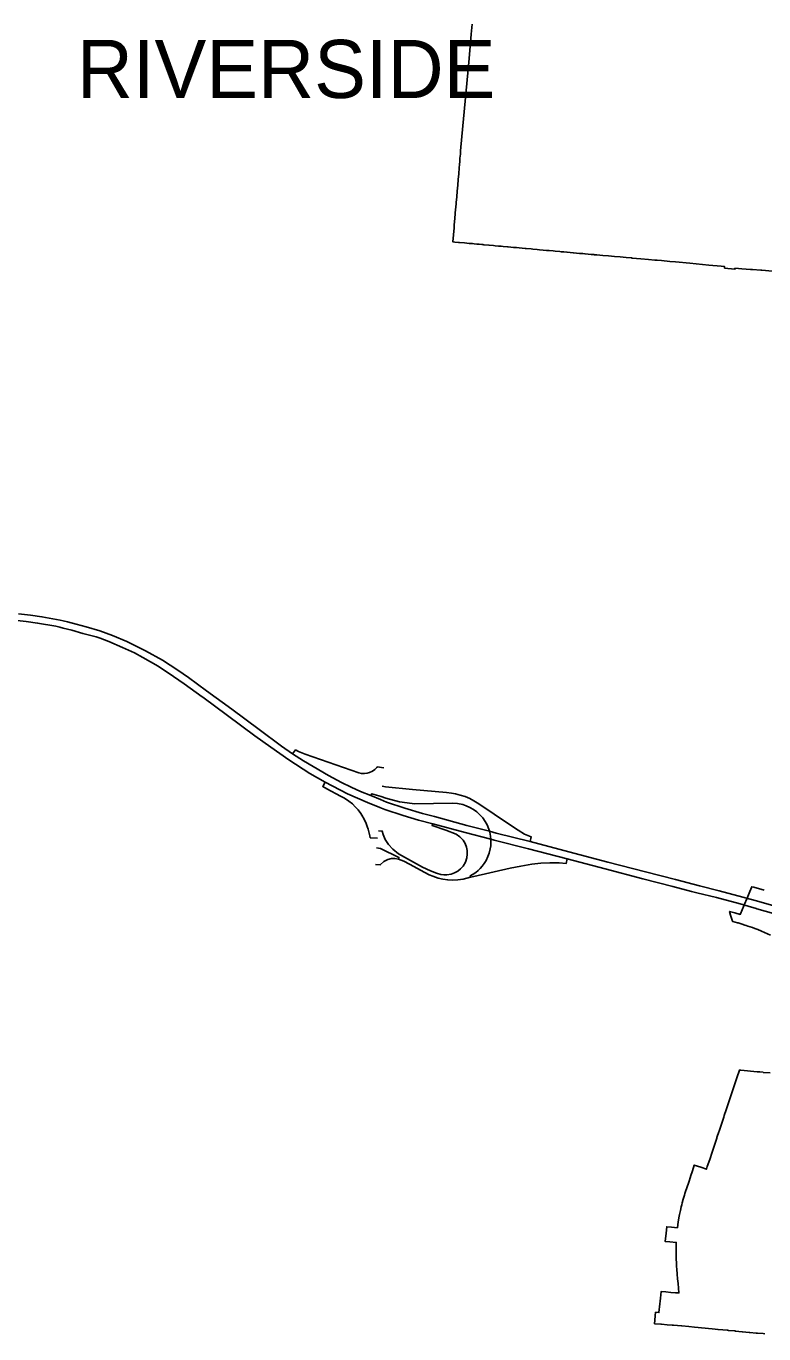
# Model space of a CAD drawing. Extents: x 0 to 34, y 0 to 22.
# Drawn here: x 5.4877 to 5.5898, y 15.0349 to 15.2158 of the extents above; entities that cross this region are included whole.
import ezdxf

# ---------------------------------------------------------------- set-up
doc = ezdxf.new("R2010")
doc.units = 0
for name, color, linetype in [('GM_X_Corporation', 7, 'Continuous'), ('GM_X_Corporation_Text', 7, 'Continuous'), ('GM_X_Interchange_Ramps', 7, 'Continuous'), ('GM_X_US_Route', 7, 'Continuous')]:
    doc.layers.add(name, color=color, linetype=linetype)

msp = doc.modelspace()

# ---------------------------------------------------------------- linework, layer by layer
at = {"layer": 'GM_X_Corporation'}
for points in [[(5.591, 15.18195), (5.5895, 15.18206), (5.58938, 15.18207), (5.58821, 15.18215), (5.58795, 15.18217), (5.58675, 15.18225), (5.58628, 15.18229), (5.58627, 15.18229), (5.58579, 15.18233), (5.58578, 15.18221), (5.58435, 15.18235), (5.58436, 15.18257), (5.58388, 15.18261), (5.58217, 15.18277), (5.57957, 15.18302), (5.57757, 15.18321), (5.57756, 15.18321), (5.57677, 15.18328), (5.57562, 15.18339), (5.57505, 15.18344), (5.57502, 15.18345), (5.57499, 15.18345), (5.57496, 15.18345), (5.57472, 15.18347), (5.57382, 15.18355), (5.57279, 15.18364), (5.57156, 15.18375), (5.57146, 15.18376), (5.57075, 15.18382), (5.56993, 15.1839), (5.56912, 15.18397), (5.56831, 15.18404), (5.5675, 15.18411), (5.56668, 15.18418), (5.5663, 15.18421), (5.56588, 15.18425), (5.56508, 15.18433), (5.56502, 15.18433), (5.56476, 15.18436), (5.56427, 15.1844), (5.56345, 15.18447), (5.56342, 15.18448), (5.56259, 15.18455), (5.56251, 15.18456), (5.56211, 15.18459), (5.56175, 15.18463), (5.56157, 15.18464), (5.56092, 15.1847), (5.56064, 15.18473), (5.56009, 15.18478), (5.5597, 15.18481), (5.55926, 15.18485), (5.55876, 15.1849), (5.55842, 15.18493), (5.55783, 15.18498), (5.55759, 15.185), (5.55689, 15.18507), (5.55676, 15.18508), (5.55595, 15.18515), (5.55555, 15.18519), (5.55555, 15.18519), (5.55515, 15.18522), (5.5544, 15.18529), (5.5543, 15.1853), (5.55373, 15.18535), (5.55346, 15.18538), (5.55306, 15.18541), (5.55261, 15.18545), (5.55238, 15.18547), (5.55176, 15.18553), (5.55171, 15.18553), (5.55104, 15.18559), (5.55091, 15.18561), (5.55074, 15.18562), (5.55037, 15.18566), (5.55006, 15.18568), (5.5497, 15.18572), (5.54946, 15.18574), (5.54921, 15.18576), (5.54903, 15.18578), (5.54837, 15.18584), (5.54836, 15.18584), (5.54768, 15.1859), (5.54755, 15.18591), (5.54701, 15.18596), (5.54701, 15.18596), (5.54675, 15.18598), (5.54675, 15.18598), (5.54675, 15.18599), (5.54692, 15.18793), (5.54695, 15.18835), (5.54698, 15.18874), (5.54708, 15.18983), (5.54714, 15.19058), (5.54715, 15.19063), (5.54721, 15.19143), (5.54728, 15.19222), (5.54735, 15.19302), (5.54742, 15.19382), (5.54749, 15.19462), (5.54756, 15.19542), (5.54762, 15.19621), (5.54766, 15.19668), (5.5477, 15.19712), (5.54774, 15.19755), (5.54779, 15.19812), (5.54783, 15.19859), (5.548, 15.20057), (5.54882, 15.20937), (5.54895, 15.21083), (5.54929, 15.21467), (5.54929, 15.2147), (5.54942, 15.2161)], [(5.54942, 15.2161), (5.54929, 15.2147), (5.54929, 15.21467), (5.54895, 15.21083), (5.54882, 15.20937), (5.548, 15.20058), (5.54783, 15.19859), (5.54779, 15.19812), (5.54774, 15.19755), (5.5477, 15.19713), (5.54766, 15.19668), (5.54762, 15.19621), (5.54756, 15.19542), (5.54749, 15.19462), (5.54742, 15.19382), (5.54735, 15.19302), (5.54728, 15.19222), (5.54721, 15.19143), (5.54715, 15.19063), (5.54714, 15.19058), (5.54708, 15.18983), (5.54698, 15.18874), (5.54695, 15.18835), (5.54692, 15.18793), (5.54692, 15.18793), (5.54675, 15.18599), (5.54675, 15.18598), (5.54675, 15.18598), (5.54701, 15.18596), (5.54701, 15.18596), (5.54755, 15.18591), (5.54768, 15.1859), (5.54836, 15.18584), (5.54837, 15.18584), (5.54903, 15.18578), (5.54921, 15.18576), (5.54946, 15.18574), (5.5497, 15.18572), (5.55006, 15.18568), (5.55037, 15.18566), (5.55074, 15.18562), (5.55091, 15.18561), (5.55104, 15.18559), (5.55171, 15.18553), (5.55176, 15.18553), (5.55238, 15.18547), (5.55261, 15.18545), (5.55306, 15.18541), (5.55346, 15.18538), (5.55373, 15.18535), (5.5543, 15.1853), (5.5544, 15.18529), (5.55515, 15.18522), (5.55555, 15.18519), (5.55555, 15.18519), (5.55595, 15.18515), (5.55676, 15.18508), (5.55689, 15.18507), (5.55759, 15.185), (5.55783, 15.18498), (5.55842, 15.18493), (5.55876, 15.1849), (5.55926, 15.18485), (5.5597, 15.18481), (5.56009, 15.18478), (5.56064, 15.18473), (5.56092, 15.1847), (5.56157, 15.18464), (5.56175, 15.18463), (5.56211, 15.18459), (5.56251, 15.18456), (5.56259, 15.18455), (5.56342, 15.18448), (5.56345, 15.18447), (5.56427, 15.1844), (5.56476, 15.18436), (5.56502, 15.18433), (5.56508, 15.18433), (5.56588, 15.18425), (5.5663, 15.18422), (5.56668, 15.18418), (5.5675, 15.18411), (5.56831, 15.18404), (5.56912, 15.18397), (5.56993, 15.1839), (5.57075, 15.18382), (5.57146, 15.18376), (5.57156, 15.18375), (5.57279, 15.18364), (5.57382, 15.18355), (5.57472, 15.18347), (5.57496, 15.18345), (5.57499, 15.18345), (5.57502, 15.18345), (5.57505, 15.18344), (5.57562, 15.18339), (5.57677, 15.18328), (5.57756, 15.18321), (5.57757, 15.18321), (5.57957, 15.18302), (5.58217, 15.18277), (5.58388, 15.18261), (5.58436, 15.18257), (5.58435, 15.18235), (5.58578, 15.18221), (5.58579, 15.18233), (5.58627, 15.18229), (5.58628, 15.18229), (5.58675, 15.18226), (5.58675, 15.18226), (5.58795, 15.18217), (5.58821, 15.18215), (5.58938, 15.18207), (5.5895, 15.18206), (5.591, 15.18195)], [(5.59072, 15.09008), (5.58946, 15.09064), (5.58897, 15.09085), (5.58855, 15.091), (5.58824, 15.09112), (5.58756, 15.09134), (5.58735, 15.09142), (5.58714, 15.09148), (5.58679, 15.0916), (5.58652, 15.09168), (5.58623, 15.09177), (5.58616, 15.0918), (5.58552, 15.09198), (5.58545, 15.09199), (5.58545, 15.092), (5.58545, 15.092), (5.5852, 15.09286), (5.58506, 15.09336), (5.5858, 15.09316), (5.58653, 15.09294), (5.58656, 15.09301), (5.58703, 15.09414), (5.58708, 15.09426), (5.58747, 15.0952), (5.58785, 15.09613), (5.58812, 15.09678), (5.58841, 15.0967), (5.58983, 15.09629)], [(5.58983, 15.09629), (5.58841, 15.0967), (5.58812, 15.09678), (5.58785, 15.09613), (5.58747, 15.0952), (5.58708, 15.09426), (5.58703, 15.09414), (5.58656, 15.09301), (5.58653, 15.09294), (5.5858, 15.09316), (5.58506, 15.09336), (5.5852, 15.09286), (5.58545, 15.092), (5.58545, 15.09199), (5.58552, 15.09198), (5.58616, 15.0918), (5.58623, 15.09177), (5.58652, 15.09168), (5.58679, 15.0916), (5.58714, 15.09148), (5.58735, 15.09142), (5.58756, 15.09134), (5.58824, 15.09112), (5.58855, 15.091), (5.58897, 15.09085), (5.58946, 15.09064), (5.59072, 15.09008)], [(5.58994, 15.03492), (5.5897, 15.03495), (5.5889, 15.03502), (5.58874, 15.03504), (5.58786, 15.03512), (5.58777, 15.03513), (5.58682, 15.03522), (5.58681, 15.03522), (5.58585, 15.03531), (5.58578, 15.03532), (5.58489, 15.0354), (5.58474, 15.03542), (5.58346, 15.03554), (5.58344, 15.03554), (5.58304, 15.03559), (5.58263, 15.03563), (5.5802, 15.03586), (5.57939, 15.03594), (5.57843, 15.03602), (5.57841, 15.03603), (5.57841, 15.03603), (5.57731, 15.03612), (5.57729, 15.03612), (5.5771, 15.03613), (5.57641, 15.03619), (5.57565, 15.03625), (5.57552, 15.03626), (5.57468, 15.03633), (5.57482, 15.03791), (5.57528, 15.03787), (5.57532, 15.03827), (5.57532, 15.03829), (5.57536, 15.03867), (5.57547, 15.03987), (5.57556, 15.04077), (5.57623, 15.04072), (5.5769, 15.04066), (5.57758, 15.04061), (5.57803, 15.04058), (5.57797, 15.04124), (5.57792, 15.04189), (5.57786, 15.04255), (5.5778, 15.0432), (5.57774, 15.04385), (5.57771, 15.04424), (5.57769, 15.04463), (5.57766, 15.04538), (5.57765, 15.04593), (5.57765, 15.04596), (5.57765, 15.04648), (5.57766, 15.04702), (5.57767, 15.04756), (5.57767, 15.04757), (5.57767, 15.04757), (5.5768, 15.04764), (5.57615, 15.04769), (5.57614, 15.04769), (5.57626, 15.04887), (5.57635, 15.04975), (5.577, 15.04969), (5.57783, 15.04961), (5.57787, 15.05001), (5.57792, 15.05041), (5.57807, 15.0512), (5.57812, 15.05145), (5.57824, 15.05198), (5.57836, 15.05251), (5.57843, 15.05278), (5.5785, 15.05304), (5.57864, 15.05357), (5.5788, 15.05409), (5.57888, 15.05435), (5.57896, 15.05461), (5.57913, 15.05513), (5.57939, 15.05592), (5.57963, 15.05666), (5.57965, 15.0567), (5.57991, 15.05748), (5.58017, 15.05826), (5.58109, 15.05796), (5.58185, 15.0577), (5.58197, 15.05808), (5.5823, 15.05906), (5.58262, 15.06004), (5.58295, 15.06101), (5.58309, 15.06145), (5.58327, 15.06199), (5.5833, 15.06207), (5.58356, 15.06286), (5.5836, 15.06297), (5.58392, 15.06395), (5.58425, 15.06492), (5.58432, 15.06514), (5.58458, 15.0659), (5.5849, 15.06688), (5.58496, 15.06704), (5.58532, 15.06813), (5.58569, 15.06923), (5.58605, 15.07033), (5.58642, 15.07142), (5.5866, 15.0714), (5.58887, 15.07118), (5.58924, 15.07115), (5.58969, 15.07111), (5.58972, 15.0711), (5.59069, 15.07101)], [(5.59069, 15.07101), (5.58972, 15.0711), (5.58969, 15.07111), (5.58924, 15.07115), (5.58887, 15.07118), (5.5866, 15.0714), (5.58642, 15.07142), (5.58605, 15.07033), (5.58569, 15.06923), (5.58532, 15.06813), (5.58496, 15.06704), (5.5849, 15.06688), (5.58458, 15.0659), (5.58432, 15.06514), (5.58425, 15.06492), (5.58392, 15.06395), (5.5836, 15.06297), (5.58356, 15.06286), (5.5833, 15.06207), (5.58327, 15.06199), (5.58309, 15.06145), (5.58295, 15.06101), (5.58262, 15.06004), (5.5823, 15.05906), (5.58197, 15.05808), (5.58185, 15.0577), (5.58109, 15.05796), (5.58017, 15.05826), (5.57991, 15.05748), (5.57965, 15.0567), (5.57963, 15.05666), (5.57939, 15.05592), (5.57913, 15.05513), (5.57896, 15.05461), (5.57888, 15.05435), (5.5788, 15.05409), (5.57864, 15.05357), (5.5785, 15.05304), (5.57843, 15.05278), (5.57836, 15.05251), (5.57824, 15.05198), (5.57812, 15.05145), (5.57807, 15.0512), (5.57792, 15.05041), (5.57787, 15.05001), (5.57783, 15.04961), (5.577, 15.04969), (5.57635, 15.04975), (5.57626, 15.04887), (5.57614, 15.04769), (5.57615, 15.04769), (5.5768, 15.04764), (5.57767, 15.04757), (5.57767, 15.04757), (5.57767, 15.04756), (5.57766, 15.04702), (5.57765, 15.04648), (5.57765, 15.04596), (5.57765, 15.04593), (5.57766, 15.04538), (5.57769, 15.04463), (5.57771, 15.04424), (5.57774, 15.04385), (5.5778, 15.0432), (5.57786, 15.04255), (5.57792, 15.04189), (5.57797, 15.04124), (5.57803, 15.04058), (5.57758, 15.04061), (5.5769, 15.04066), (5.57623, 15.04072), (5.57556, 15.04077), (5.57547, 15.03987), (5.57536, 15.03867), (5.57532, 15.03829), (5.57532, 15.03827), (5.57528, 15.03787), (5.57482, 15.03791), (5.57468, 15.03633), (5.57552, 15.03626), (5.57565, 15.03625), (5.57641, 15.03619), (5.5771, 15.03613), (5.57729, 15.03612), (5.57731, 15.03612), (5.57841, 15.03603), (5.57841, 15.03603), (5.57843, 15.03602), (5.57939, 15.03594), (5.5802, 15.03586), (5.58263, 15.03563), (5.58304, 15.03559), (5.58344, 15.03554), (5.58346, 15.03554), (5.58474, 15.03542), (5.58489, 15.0354), (5.58578, 15.03532), (5.58585, 15.03531), (5.58681, 15.03522), (5.58682, 15.03522), (5.58777, 15.03513), (5.58786, 15.03512), (5.58874, 15.03504), (5.5889, 15.03502), (5.5897, 15.03495), (5.58994, 15.03492)]]:
    msp.add_lwpolyline(points, dxfattribs=at)
at = {"layer": 'GM_X_Interchange_Ramps'}
for points in [[(5.5372, 15.11324), (5.53628, 15.11336), (5.53621, 15.11326), (5.53593, 15.11298), (5.53564, 15.11277), (5.53523, 15.11257), (5.53488, 15.11247), (5.53453, 15.11242), (5.53409, 15.11244), (5.53373, 15.11253), (5.52633, 15.11511), (5.5254, 15.11547), (5.52498, 15.1157), (5.52456, 15.11518)], [(5.5291, 15.11123), (5.52874, 15.11063), (5.52931, 15.1103), (5.5312, 15.10932), (5.53176, 15.10903), (5.53236, 15.10863), (5.53285, 15.10824), (5.53325, 15.10785), (5.53365, 15.10741), (5.53403, 15.1069), (5.53431, 15.10645), (5.53436, 15.10635)], [(5.5492, 15.09809), (5.54916, 15.09827), (5.54958, 15.09852), (5.54992, 15.09876), (5.55025, 15.09903), (5.55054, 15.09931), (5.55081, 15.09961), (5.55108, 15.09998), (5.55136, 15.10042), (5.55161, 15.10094), (5.55178, 15.1014), (5.55193, 15.10202), (5.55199, 15.10243), (5.55202, 15.10301), (5.55201, 15.10334), (5.55197, 15.10373), (5.55191, 15.10411), (5.55181, 15.10445), (5.55174, 15.10473), (5.55149, 15.10532), (5.55122, 15.10581), (5.55088, 15.1063), (5.55049, 15.10674), (5.55005, 15.10714), (5.5496, 15.10747), (5.54912, 15.10775), (5.5486, 15.10798), (5.54814, 15.10813), (5.54738, 15.10829), (5.54669, 15.10836), (5.54142, 15.10826), (5.54042, 15.10838), (5.53938, 15.10853), (5.53748, 15.10905), (5.53681, 15.10926), (5.53556, 15.10964), (5.53542, 15.10938)], [(5.54117, 15.11024), (5.53742, 15.11061), (5.53695, 15.11068)], [(5.55745, 15.10302), (5.55761, 15.10367), (5.55665, 15.10407), (5.55578, 15.10459), (5.55461, 15.1054), (5.55033, 15.10826), (5.54967, 15.10867), (5.54908, 15.10898), (5.54845, 15.10924), (5.54778, 15.10946), (5.54714, 15.10962), (5.54657, 15.10972), (5.54585, 15.10979), (5.54117, 15.11024)], [(5.53436, 15.10635), (5.53458, 15.10594), (5.53475, 15.10554), (5.5349, 15.10513), (5.53502, 15.10473), (5.53526, 15.10383), (5.53532, 15.10355), (5.53633, 15.10349)], [(5.54398, 15.10548), (5.54387, 15.10525), (5.54579, 15.10462), (5.54722, 15.10405), (5.54773, 15.10368), (5.54816, 15.10321), (5.54844, 15.10274), (5.54863, 15.10224), (5.54872, 15.10177), (5.54874, 15.10129), (5.54867, 15.10077), (5.54848, 15.10019), (5.54816, 15.09964), (5.54783, 15.09926), (5.54745, 15.09895), (5.54698, 15.09868), (5.5465, 15.0985), (5.54591, 15.09841), (5.5455, 15.09841), (5.5451, 15.09846), (5.54447, 15.09867), (5.54367, 15.09896), (5.54254, 15.09947), (5.53925, 15.10135), (5.53845, 15.10196), (5.53785, 15.1026), (5.5374, 15.10333), (5.5371, 15.10398), (5.53698, 15.10447), (5.53644, 15.10451)], [(5.5362, 15.10214), (5.53676, 15.10208), (5.53928, 15.10084), (5.53923, 15.10057)], [(5.53605, 15.09987), (5.53671, 15.0998), (5.53718, 15.10026), (5.53777, 15.10053), (5.53824, 15.10068), (5.53871, 15.10067), (5.53923, 15.10057), (5.53997, 15.10031), (5.54076, 15.09989), (5.54287, 15.09874), (5.54349, 15.09843), (5.54398, 15.09823), (5.54473, 15.09798), (5.54538, 15.09783), (5.54604, 15.09772), (5.54671, 15.09767), (5.54746, 15.09772), (5.54817, 15.09783), (5.5492, 15.09809), (5.54965, 15.0982), (5.55468, 15.09933), (5.55618, 15.09962), (5.55766, 15.09989), (5.55894, 15.10004), (5.56019, 15.10009), (5.56146, 15.10009), (5.56242, 15.09999), (5.56258, 15.10063)]]:
    msp.add_lwpolyline(points, dxfattribs=at)
at = {"layer": 'GM_X_US_Route'}
for points in [[(5.48664, 15.13452), (5.48831, 15.13434), (5.48988, 15.13412), (5.49239, 15.13367), (5.4928, 15.13357), (5.49342, 15.13342), (5.49462, 15.13311), (5.49599, 15.13274), (5.49789, 15.13216), (5.49963, 15.13154), (5.50163, 15.13072), (5.50421, 15.12941), (5.50657, 15.12812), (5.50867, 15.12673), (5.51015, 15.12571), (5.51266, 15.12388), (5.51615, 15.12133), (5.51996, 15.11852), (5.52305, 15.11622), (5.52456, 15.11518), (5.5261, 15.11418), (5.52742, 15.1134), (5.52953, 15.11216), (5.53132, 15.11121), (5.53269, 15.11053), (5.53395, 15.10997), (5.53542, 15.10938), (5.53675, 15.10883), (5.53759, 15.10849), (5.54012, 15.10763), (5.54255, 15.10691), (5.54423, 15.10647), (5.54869, 15.10527), (5.55181, 15.10445), (5.55273, 15.10421), (5.55745, 15.10302), (5.56282, 15.10162), (5.56819, 15.10019), (5.5734, 15.09884), (5.57756, 15.09779), (5.58087, 15.09689), (5.58361, 15.09622), (5.58689, 15.09534), (5.58908, 15.09472), (5.59148, 15.09402)], [(5.46895, 15.13431), (5.47215, 15.13421), (5.4747, 15.13411), (5.47717, 15.13401), (5.48142, 15.1339), (5.48394, 15.13378), (5.48604, 15.13366), (5.48771, 15.13348), (5.48928, 15.13326), (5.49179, 15.13281), (5.49235, 15.13268), (5.49282, 15.13256), (5.49402, 15.13225), (5.49556, 15.13183), (5.49738, 15.13136), (5.49794, 15.13115)], [(5.49794, 15.13115), (5.49913, 15.1307), (5.50103, 15.12987), (5.50269, 15.12912), (5.50385, 15.12848), (5.50598, 15.12727), (5.50807, 15.12587), (5.50955, 15.12485), (5.51206, 15.12303), (5.51213, 15.12298)], [(5.51213, 15.12298), (5.51555, 15.12047), (5.51936, 15.11766), (5.52157, 15.11607), (5.52403, 15.11433), (5.52694, 15.11243), (5.5291, 15.11123), (5.53218, 15.10964), (5.53494, 15.10841), (5.53665, 15.10775), (5.53735, 15.10747), (5.53987, 15.10664), (5.54201, 15.10597), (5.54398, 15.10548), (5.54844, 15.10428), (5.55201, 15.10334), (5.55248, 15.10321), (5.5572, 15.10203), (5.56258, 15.10063), (5.56784, 15.09924), (5.57304, 15.09788), (5.5772, 15.09683), (5.57979, 15.09614)], [(5.57979, 15.09614), (5.58051, 15.09594), (5.58325, 15.09527), (5.58653, 15.09439), (5.58872, 15.09376), (5.5888, 15.09374)], [(5.5888, 15.09374), (5.59112, 15.09307), (5.59352, 15.09228), (5.59591, 15.0914), (5.59838, 15.09043), (5.60151, 15.08924), (5.60708, 15.08711), (5.60852, 15.08656), (5.61592, 15.08366), (5.6197, 15.08222), (5.61993, 15.08213)]]:
    msp.add_lwpolyline(points, dxfattribs=at)

# ---------------------------------------------------------------- texts
at = {"layer": 'GM_X_Corporation_Text'}
msp.add_text('RIVERSIDE', height=0.008037, rotation=0, dxfattribs=at).set_placement((5.49471, 15.20589))

doc.saveas('drawing.dxf')
